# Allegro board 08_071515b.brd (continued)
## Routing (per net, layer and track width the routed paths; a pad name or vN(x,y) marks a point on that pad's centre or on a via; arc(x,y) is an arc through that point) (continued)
VDD_PLL: length 19.3
  TOP w0.203: U1.K6 v1(29.02,54.14) ; U1.L6 v1(29.02,52.54) ; U1.M7 v1(29.82,51.74)
  TOP w0.305: U1.K6 U1.L6 ; U1.L7 U1.M7
  BOTTOM w0.305: 29.73,53.23 C242.1 29.69,54.14 v1(29.02,54.14) ; 29.73,53.23 C244.1 ; 29.73,53.23 C46.1 25.74,53.23 25.53,53.44 C243.1 20.17,53.44 ; C244.1 29.82,52.48 v1(29.82,51.74) ; C244.1 29.69,52.54 v1(29.02,52.54)
  BOTTOM w0.508: 20.17,53.44 C47.1 18.39,53.44 L1.2
VDD_REF: length 163.5
  TOP w0.203: U1.P5 v1(28.22,50.14) U1.R5
  TOP w0.305: v1(33.82,55.74) U1.G11 U1.G10 ; U1.T9 v1(31.42,48.54) ; v1(46.22,48.54) C129.1 ; v1(46.22,50.14) C67.1 ; v1(33.82,43.34) C149.1 ; v1(46.22,46.94) C72.1 ; U1.T15 v1(37.02,48.54) ; U1.T10 v1(32.22,48.54) ; v1(43.02,50.14) C133.1 ; v1(43.02,46.94) C62.1 ; U1.M15 v1(37.02,51.74) ; C109.1 34.99,43.71 v1(35.42,44.14) ; U1.T6 v1(29.82,48.54) U1.T7 ; C82.1 v1(43.02,48.54) ; U1.T8 v1(30.62,48.54) ; v1(6.98,8.26) R43.1 ; U1.T13 v1(35.42,48.54) ; v1(3.17,8.38) R42.1 ; U1.N15 v1(37.02,50.94) ; U1.T12 v1(34.62,48.54) ; U1.P15 v1(37.02,50.14) ; U1.R15 v1(37.02,49.34) ; v1(46.22,51.74) C77.1 ; C87.1 v1(46.22,45.34) ; U1.T11 v1(33.82,48.54) ; U1.T14 v1(36.22,48.54)
  TOP w0.508: v2(13.59,47.75) C201.1 14.36,46.77 Y2.4 12.71,46.48 R113.1 ; v2(59.69,51.43) R16.1 ; FL3.1 v2(57.58,49.78)
  TOP w0.635: v2(59.69,54.48) 59.25,54.93 FL2.1
  L5_SIG w0.508: v2(28.19,44.2) 24.38,44.2 22.86,45.72 15.62,45.72 v2(13.59,47.75)
  L6_PWR w0.508: 62.15,57.99 TP4.1 60.02,57.99
  BOTTOM w0.305: v1(43.02,46.94) C121.1 ; v1(50.55,49.4) 50.55,48.62 C57.1 51.31,48.62 v1(51.31,49.4) ; C105.1 v1(46.22,50.14) ; C145.1 v1(43.02,48.54) ; C101.1 v1(46.22,46.94) ; v1(46.22,45.34) C125.1 ; C113.1 v1(43.02,50.14) ; C137.1 34.53,55.74 v1(33.82,55.74) ; C92.1 v1(46.22,51.74) ; C149.1 v1(33.82,43.34) ; C141.1 v1(46.22,48.54) ; v1(43.02,45.34) C97.1
  BOTTOM w0.381: v1(3.17,8.38) 3.73,7.82 6.55,7.82 v1(6.98,8.26) 8.13,8.26 10.35,10.48 19.75,10.48 20.45,11.18 22.86,11.18 24.13,9.91 35.11,9.91 35.62,10.41 37.47,10.41 38.1,9.78 48.39,9.78 49.02,10.41 49.02,16.38 47.85,17.56 47.85,20.29 46.67,21.46 46.67,25.15 47.5,25.97 47.5,27.81 48.01,28.32 51.44,28.32 51.82,28.7 51.82,43.56 53.09,44.83 53.09,50.67 53.85,51.43 v2(59.69,51.43) ; v1(35.42,44.14) 35.42,43.44 C52.1 36.22,43.44 v1(36.22,44.14)
  vias: v2(60.45,57.53) v2(60.45,56.77) v2(60.45,56.01) v2(61.47,57.53) v2(61.47,56.77) v2(61.47,56.01)
AUDIO_CLK: length 8.1
  BOTTOM w0.14: J3.40 8.25,31.88 8.26,31.88 9.65,31.88 10.16,31.37 11.05,31.37 12.19,32.51 R141.2
CLK1: length 6.5
  BOTTOM w0.14: R142.2 10.69,29.18 10.22,29.65 10.22,30.54 9.52,31.24 J3.42
CLK2: length 7.5
  BOTTOM w0.14: R144.2 11.87,27.81 11.3,28.38 10.48,28.38 9.53,29.34 9.53,30.35 9.27,30.61 J3.44
CON_RESET_IN*: length 85.9
  TOP w0.14: U11.2 56.26,38.73 55.82,38.29 v1(54.61,38.29)
  L5_SIG w0.127: v1(54.23,12.45) 53.59,13.08 53.59,20.07 53.98,20.45 54.85,20.45 55.37,20.97 55.37,21.84 55.12,22.1 54.23,22.1 53.7,22.63 53.7,37.38 v1(54.61,38.29)
  L8_SIG w0.127: v1(54.23,12.45) 51.82,12.45 48.77,9.4 39.5,9.4 38.67,8.57 11.75,8.57 8,12.32 8,13.72 v1(8.51,14.22)
  BOTTOM w0.14: J3.96 6.91,14.22 v1(8.51,14.22) ; R62.2 v1(54.61,38.29)
DAI0_PIN01: length 60.8
  TOP w0.203: U1.Y8 v1(30.62,45.34)
  L8_SIG w0.127: v1(59.14,13.46) 58.65,13.46 57.79,13.46 55.93,15.32 55.93,27.13 55.25,27.81 55.25,29.59 54.61,30.23 54.61,31.24 55.12,31.75 55.12,35.69 54.74,36.07 54.1,36.07 50.55,39.62 48.9,39.62 47.4,38.13 42.55,38.13 41.13,39.54 40.36,39.54 40.09,39.54 40.09,39.54 40.05,39.54 38.84,40.74 34.86,40.74 34.17,40.06 33.22,40.06 32.89,40.39 30.35,40.39 29.86,40.88 29.86,44.58 v1(30.62,45.34)
  BOTTOM w0.14: J1.3 v1(59.14,13.46)
DAI0_PIN02: length 60.9
  TOP w0.203: U1.V9 v1(31.42,46.94)
  L8_SIG w0.127: v1(31.42,46.94) 31.42,46.91 31.03,46.53 31.03,44.88 30.19,44.03 30.19,42.33 30.86,41.66 32.26,41.66 33.53,40.39 34.04,40.39 34.72,41.07 39.02,41.07 40.22,39.87 41.27,39.87 42.68,38.46 47.22,38.46 48.77,40.01 50.8,40.01 54.36,36.45 55.18,36.45 55.58,36.05 55.58,28.12 56.26,27.43 56.26,15.62 57.78,14.1 v1(58.42,14.1)
  BOTTOM w0.14: J1.5 v1(58.42,14.1)
DAI0_PIN03: length 56.5
  TOP w0.203: U1.W9 v1(31.42,46.14)
  L8_SIG w0.127: v1(59.14,14.73) 59.14,15.26 58.4,16 58.17,16 56.92,17.25 56.92,27.79 56.39,28.32 56.39,37.47 56.01,37.85 53.98,37.85 50.89,40.93 40.1,40.93 39.24,41.78 33.15,41.78 32.51,42.42 31.88,42.42 31.46,42.84 31.46,44.28 31.83,44.66 31.83,45.73 v1(31.42,46.14)
  BOTTOM w0.14: J1.7 v1(59.14,14.73)
DAI0_PIN04: length 56.5
  TOP w0.203: U1.Y9 v1(31.42,45.34)
  L8_SIG w0.127: v1(58.42,15.37) 57.78,15.37 56.59,16.56 56.59,27.61 56.01,28.19 56.01,36.45 55.63,36.83 54.48,36.83 50.93,40.39 48.64,40.39 47.04,38.79 42.82,38.79 41.41,40.2 40.36,40.2 39.16,41.4 33.02,41.4 32.38,42.04 31.75,42.04 31.05,42.74 31.05,44.39 31.42,44.76 v1(31.42,45.34)
  BOTTOM w0.14: J1.9 v1(58.42,15.37)
DAI0_PIN05: length 56.2
  TOP w0.203: U1.W10 v1(32.22,46.14)
  L8_SIG w0.127: v1(61.5,16) 57.58,19.92 57.58,28.06 57.15,28.49 57.15,39.5 56.82,39.83 53.75,39.83 51.87,41.71 40.63,41.71 39.79,42.55 33.4,42.55 32.65,43.29 32.65,45.71 v1(32.22,46.14)
  BOTTOM w0.14: v1(61.5,16) 61.5,16 J1.11
DAI0_PIN06: length 56.3
  TOP w0.203: U1.V10 v1(32.22,46.94)
  L8_SIG w0.127: v1(32.22,46.94) 33.02,46.14 33.02,43.43 33.55,42.91 39.9,42.91 40.77,42.04 52.07,42.04 53.34,40.77 56.39,40.77 57.53,39.62 57.53,28.58 57.91,28.2 57.91,20.22 v1(61.5,16.64)
  BOTTOM w0.14: J1.13 v1(61.5,16.64)
DAI0_PIN07: length 53.4
  TOP w0.203: U1.Y10 v1(32.22,45.34)
  L8_SIG w0.127: v1(32.22,45.34) 32.22,44.54 31.79,44.11 31.79,42.97 31.96,42.8 32.64,42.8 33.27,42.16 39.5,42.16 40.39,41.28 51.05,41.28 53.47,38.86 56.52,38.86 56.77,38.61 56.77,28.41 57.25,27.92 57.25,19.16 v1(59.14,17.27)
  BOTTOM w0.14: J1.15 v1(59.14,17.27)
DAI0_PIN08: length 56.7
  TOP w0.203: U1.W11 v1(33.82,46.14)
  L8_SIG w0.127: v1(61.5,17.91) 61.98,17.91 61.98,17.91 62.23,17.91 62.53,18.21 62.53,18.75 61.6,19.68 60.83,19.68 60.2,20.32 60.2,30.73 59.56,31.37 59.56,42.42 59.05,42.93 57.4,42.93 57.02,43.31 48.26,43.31 46.99,44.58 34.42,44.58 34.23,44.76 34.23,45.73 v1(33.82,46.14)
  BOTTOM w0.14: J1.17 v1(61.5,17.91)
DAI0_PIN09: length 55.6
  TOP w0.203: U1.V11 v1(33.82,46.94)
  L8_SIG w0.127: v1(33.82,46.94) 33.4,46.52 33.4,44.45 34.44,43.41 40.03,43.41 41.02,42.42 52.58,42.42 53.21,41.78 56.01,41.78 58.67,39.12 58.67,32.38 58.37,32.08 58.37,30.53 59.31,29.59 59.31,19.94 60.71,18.54 61.62,18.54 v1(62.1,18.54)
  BOTTOM w0.14: J1.19 v1(62.1,18.54)
DAI0_PIN10: length 53.3
  TOP w0.203: U1.Y11 v1(33.82,45.34)
  L8_SIG w0.127: v1(61.5,19.18) 60.71,19.18 59.82,20.07 59.82,30.48 59.23,31.06 59.23,42.11 58.8,42.55 57.15,42.55 56.72,42.98 48.34,42.98 48.34,42.98 48.12,42.98 47.67,43.43 40.64,43.43 40.39,43.69 34.8,43.69 33.82,44.67 v1(33.82,45.34)
  BOTTOM w0.14: J1.21 v1(61.5,19.18)
DAI0_PIN11: length 56.6
  TOP w0.203: U1.Y12 v1(34.62,45.34)
  L8_SIG w0.127: v1(62.1,19.81) 61.9,20.02 61.01,20.02 60.58,20.45 60.58,30.99 59.94,31.62 59.94,45.34 59.44,45.85 56.86,45.85 55.46,44.45 47.92,44.45 46.52,45.85 45.21,45.85 44.32,44.95 43.18,44.95 35.01,44.95 v1(34.62,45.34)
  BOTTOM w0.14: J1.23 v1(62.1,19.81)
DAI0_PIN12: length 57.8
  TOP w0.203: U1.W12 v1(34.62,46.14)
  L8_SIG w0.127: v1(34.62,46.14) 34.62,46.15 34.23,46.54 34.23,47.13 34.46,47.35 41.89,47.35 42.04,47.5 46.61,47.5 47.88,46.23 48.9,46.23 49.45,45.67 53.92,45.67 55.25,46.99 59.78,46.99 61.04,45.73 61.04,32.31 62.23,31.11 62.23,21.18 v1(61.5,20.45)
  BOTTOM w0.14: J1.25 v1(61.5,20.45)
DAI0_PIN19: length 49.6
  TOP w0.203: U1.W13 v1(35.42,46.14)
  L8_SIG w0.127: v1(35.42,46.14) 35.83,45.73 42.55,45.73 43.05,46.23 46.61,46.23 48.01,44.83 55.37,44.83 56.77,46.23 59.56,46.23 60.33,45.47 60.33,31.88 60.96,31.24 60.96,25.43 v1(61.5,24.89)
  BOTTOM w0.14: J1.39 v1(61.5,24.89)
DAI0_PIN20: length 50
  TOP w0.203: U1.V12 v1(34.62,46.94)
  L8_SIG w0.127: v1(61.5,25.53) 61.29,25.74 61.29,31.55 60.71,32.13 60.71,45.59 59.69,46.61 56.64,46.61 55.25,45.21 49.4,45.21 48.83,45.78 47.61,45.78 46.86,46.53 35.03,46.53 v1(34.62,46.94)
  BOTTOM w0.14: J1.41 v1(61.5,25.53)
DAI1_PIN01: length 56.3
  TOP w0.203: U1.R20 v1(41.02,49.34)
  L4_SIG w0.127: v1(54.27,13.46) 54.65,13.84 54.65,14.32 54.94,14.61 58.29,14.61 58.85,15.16 59.49,15.16 60.15,15.82 60.15,27.33 58.85,28.63 58.85,29.9 57.94,30.81 57.94,33.05 53.64,37.34 53.64,38.59 52.05,40.18 52.05,44.85 51.31,45.59 51.31,47.12 49.09,49.34 v1(41.02,49.34)
  BOTTOM w0.14: J1.4 v1(54.27,13.46)
DAI1_PIN02: length 57.6
  TOP w0.203: U1.P18 v1(39.42,50.14)
  L4_SIG w0.127: v1(55.16,14.1) 55.66,13.59 58.65,13.59 60.48,15.41 60.48,27.58 59.18,28.88 59.18,30.16 58.29,31.05 58.29,33.16 53.98,37.47 53.98,39.88 52.38,41.47 52.38,47.06 51.82,47.62 51.44,47.62 49.35,49.71 42.08,49.71 42.04,49.75 39.81,49.75 v1(39.42,50.14)
  BOTTOM w0.14: J1.6 v1(55.16,14.1)
DAI1_PIN03: length 55.7
  TOP w0.203: U1.R18 v1(39.42,49.34)
  L4_SIG w0.127: v1(39.42,49.34) 39.81,48.95 42.1,48.95 42.16,49.02 46.74,49.02 47.88,47.88 50.04,47.88 50.9,47.02 50.9,45.53 51.69,44.75 51.69,40.08 53.31,38.45 53.31,37.2 57.39,33.13 57.39,33.12 57.58,32.93 57.58,28.53 59.82,26.29 59.82,16.97 59.36,16.51 58.93,16.51 58.29,15.87 57.66,15.87 56.72,14.94 54.47,14.94 v1(54.27,14.73)
  BOTTOM w0.14: J1.8 v1(54.27,14.73)
DAI1_PIN04: length 47.8
  TOP w0.203: U1.T20 v1(41.02,48.54)
  L4_SIG w0.127: v1(55.16,15.37) 57.15,17.36 57.15,19.94 57.81,20.6 57.81,27.69 57.25,28.25 57.25,32.79 57.06,32.98 57.06,32.99 52.98,37.06 52.98,38.32 51.36,39.94 51.36,44.61 50.57,45.4 50.57,46.71 49.78,47.5 47.37,47.5 46.91,47.96 42.09,47.96 41.5,48.54 v1(41.02,48.54)
  BOTTOM w0.14: J1.10 v1(55.16,15.37)
DAI1_PIN05: length 46.7
  TOP w0.203: U1.U20 v1(41.02,47.74)
  L4_SIG w0.127: v1(41.02,47.74) 41.29,47.74 41.66,47.37 46.48,47.37 48.01,45.85 49.19,45.85 50.7,44.34 50.7,43.62 50.7,39.67 52.32,38.04 52.32,36.79 56.4,32.72 56.4,32.71 56.59,32.52 56.59,27.98 57.15,27.41 57.15,20.87 56.46,20.19 56.46,17.97 55.64,17.15 55.63,17.15 54.86,17.14 54.27,16.55 v1(54.27,16)
  BOTTOM w0.14: J1.12 v1(54.27,16)
DAI1_PIN06: length 46.3
  TOP w0.203: U1.T19 v1(40.22,48.54)
  L4_SIG w0.127: v1(40.22,48.54) 40.63,48.13 41.41,48.13 41.88,47.65 46.71,47.65 48.13,46.23 49.27,46.23 51.03,44.47 51.03,43.93 51.03,39.81 52.65,38.18 52.65,36.93 56.73,32.85 56.73,32.84 56.92,32.66 56.92,28.11 57.48,27.55 57.48,20.74 56.79,20.05 56.79,17.81 55.63,16.64 v1(55.16,16.64)
  BOTTOM w0.14: J1.14 v1(55.16,16.64)
DAI1_PIN07: length 46.4
  TOP w0.203: U1.U19 v1(40.22,47.74)
  L4_SIG w0.127: v1(54.27,17.27) 54.47,17.48 55.5,17.48 56.13,18.11 56.13,20.32 56.77,20.96 56.77,27.33 56.26,27.84 56.26,32.38 56.07,32.57 56.07,32.58 51.94,36.7 51.94,37.47 51.56,37.85 50.55,37.85 50.37,38.03 50.37,44.2 49.86,44.71 48.58,44.71 46.74,46.55 41.97,46.55 41.17,47.35 40.61,47.35 v1(40.22,47.74)
  BOTTOM w0.14: J1.16 v1(54.27,17.27)
DAI1_PIN08: length 57
  TOP w0.203: U1.R19 v1(40.22,49.34)
  L5_SIG w0.127: v1(55.16,17.91) 57.62,17.91 60.68,20.97 60.68,45.88 59.31,47.24 54.1,47.24 52.53,45.67 49.58,45.67 49.02,46.23 44.45,46.23 41.75,48.93 40.63,48.93 v1(40.22,49.34)
  BOTTOM w0.14: J1.18 v1(55.16,17.91)
DAI1_PIN09: length 58.2
  TOP w0.203: U1.T18 v1(39.42,48.54)
  L5_SIG w0.127: v1(54.27,18.54) 57.79,18.54 60.35,21.11 60.35,45.74 59.18,46.91 54.24,46.91 52.66,45.34 49.44,45.34 48.94,45.85 43.55,45.85 41.28,48.13 39.83,48.13 v1(39.42,48.54)
  BOTTOM w0.14: J1.20 v1(54.27,18.54)
DAI1_PIN10: length 55.6
  TOP w0.203: U1.U18 v1(39.42,47.74)
  L5_SIG w0.127: v1(39.42,47.74) 39.81,47.35 41.42,47.35 42.23,46.55 42.23,45.53 42.93,44.83 52.62,44.83 54.38,46.58 59.04,46.58 60.02,45.6 60.02,21.35 57.85,19.18 v1(55.16,19.18)
  BOTTOM w0.14: J1.22 v1(55.16,19.18)
DAI1_PIN11: length 41.2
  TOP w0.203: U1.V19 v1(40.22,46.94)
  L4_SIG w0.127: v1(54.27,19.81) 54.27,20.3 54.42,20.45 54.74,20.45 56.01,21.72 56.01,27.05 55.56,27.5 55.56,31.05 53.21,33.4 53.21,34.16 51.82,35.56 50.67,35.56 49.53,36.7 49.53,42.1 46.86,44.77 46.86,45.45 46.47,45.85 41.31,45.85 v1(40.22,46.94)
  BOTTOM w0.14: J1.24 v1(54.27,19.81)
DAI1_PIN12: length 39.1
  TOP w0.203: U1.V20 v1(41.02,46.94)
  L4_SIG w0.127: v1(55.46,20.45) 56.39,21.37 56.39,27.24 55.92,27.7 55.92,31.16 53.59,33.49 53.59,34.54 51.56,36.58 50.8,36.58 50.04,37.34 50.04,44.06 49.72,44.38 48.33,44.38 46.58,46.13 41.83,46.13 v1(41.02,46.94)
  BOTTOM w0.14: J1.26 v1(55.46,20.45)
DAI1_PIN19: length 49.3
  TOP w0.203: U1.V17 v1(38.62,46.94)
  L5_SIG w0.127: v1(55.46,24.89) 58.87,24.89 59.69,25.72 59.69,45.47 58.9,46.25 54.51,46.25 52.71,44.45 42.67,44.45 40.6,46.53 39.03,46.53 v1(38.62,46.94)
  BOTTOM w0.14: J1.40 v1(55.46,24.89)
DAI1_PIN20: length 33.2
  TOP w0.203: U1.W18 v1(39.42,46.14)
  L4_SIG w0.127: v1(55.46,25.53) 54.99,26 54.99,29.97 52.71,32.26 52.71,33.91 52.32,34.29 50.8,34.29 49.15,35.94 49.15,42.01 46.33,44.83 41.66,44.83 40.76,45.73 39.83,45.73 39.42,46.13 v1(39.42,46.14)
  BOTTOM w0.14: v1(55.46,25.53) J1.42
DMC0_A00: length 41.1
  TOP w0.14: U8.N3 v1(36.22,74.34)
  TOP w0.203: U1.D19 v1(40.22,58.94)
  L4_SIG w0.127: v1(42.62,59.74) 43.19,60.31 44.22,61.34 44.22,64.61 44.07,64.76 44.07,70.14 44.27,70.34 45.14,70.34 45.34,70.54 45.34,75.74 44.94,76.14 36.82,76.14 36.62,75.94 U8.N3 v1(36.22,74.34)
  BOTTOM w0.14: v1(42.62,59.74) 42.22,59.34 40.62,59.34 v1(40.22,58.94) ; v1(36.22,74.34) 36.22,74.74 37.22,75.74 37.42,75.74 37.62,75.54 37.62,75.34 37.82,75.14 38.02,75.14 38.22,75.34 38.22,75.47 38.42,75.67 38.62,75.67 38.82,75.47 38.82,75.34 39.02,75.14 39.22,75.14 39.42,75.34 39.42,75.54 39.22,75.74 39.22,75.94 39.42,76.14 41.37,76.14 41.42,76.19 41.93,76.19 RN1.1
DMC0_A01: length 41.3
  TOP w0.14: U8.P7 v1(37.02,78.34)
  TOP w0.203: U1.D20 v1(41.02,58.94)
  L8_SIG w0.127: v1(41.02,58.94) 40.62,59.34 39.22,59.34 39.02,59.14 39.02,58.74 38.82,58.54 38.42,58.54 38.22,58.74 38.22,59.94 38.42,60.14 38.82,60.14 39.02,60.34 39.02,63.34 38.82,63.54 37.62,63.54 37.42,63.74 37.42,63.94 37.62,64.14 37.82,64.14 38.02,63.94 38.82,63.94 39.02,64.14 39.02,64.34 38.82,64.54 38.02,64.54 37.82,64.74 37.82,68.81 38.22,69.21 38.22,69.74 37.82,70.14 37.82,70.34 38.02,70.54 38.02,71.34 37.82,71.54 37.82,71.74 38.02,71.94 38.22,71.94 38.42,72.14 38.42,72.34 38.22,72.54 38.22,74.94 37.82,75.34 37.82,75.54 38.02,75.74 38.22,75.74 38.42,75.54 38.62,75.54 38.82,75.74 38.82,75.94 38.62,76.14 37.22,76.14 37.02,76.34 v1(37.02,78.34)
  BOTTOM w0.14: RN3.2 42.01,79.89 41.42,79.89 41.17,80.14 41.02,80.14 40.82,80.34 40.82,80.54 41.02,80.74 41.02,80.94 40.82,81.14 40.42,81.14 40.22,80.94 40.22,80.74 40.42,80.54 40.42,80.34 40.22,80.14 39.62,80.14 39.42,79.94 39.42,79.42 39.5,79.34 39.5,78.94 39.3,78.74 37.42,78.74 37.42,78.74 v1(37.02,78.34)
DMC0_A02: length 41.4
  TOP w0.127: U1.C20 41.42,59.34 v1(41.82,59.74)
  TOP w0.14: U8.P3 v1(37.02,74.34)
  L4_SIG w0.127: v1(37.02,74.34) 37.02,75.54 37.22,75.74 44.43,75.74 44.83,75.34 44.83,71.14 44.63,70.94 43.42,70.94 43.22,70.74 43.22,66.34 43.02,66.14 42.55,66.14 42.42,66.01 42.42,65.66 42.55,65.53 43.56,65.53 43.69,65.4 43.69,64.39 43.82,64.26 43.82,61.94 43.62,61.74 43.42,61.74 43.22,61.94 43.02,61.94 42.82,61.74 42.42,61.74 42.06,62.1 41.75,62.1 41.62,61.98 41.62,60.34 41.82,60.14 v1(41.82,59.74)
  BOTTOM w0.14: v1(37.02,74.34) 37.42,73.94 39.14,73.94 39.42,73.66 39.42,71.94 39.62,71.74 41.22,71.74 41.42,71.94 41.42,73.35 41.56,73.49 42.01,73.49 RN2.2
DMC0_A03: length 41.3
  TOP w0.14: U8.N2 v1(36.22,73.54)
  TOP w0.203: U1.C19 v1(40.22,59.74)
  L4_SIG w0.127: v1(36.22,61.34) 36.22,61.94 35.62,62.54 35.22,62.54 35.02,62.74 35.02,64.94 35.22,65.14 36.42,65.14 36.62,65.34 36.62,65.73 37.02,66.13 37.02,66.41 37.22,66.61 37.42,66.61 37.62,66.41 37.82,66.41 38.02,66.61 38.02,66.81 37.82,67.01 37.22,67.01 37.02,67.21 37.02,67.41 37.22,67.61 37.42,67.61 37.62,67.41 37.82,67.41 38.02,67.61 38.02,67.81 37.82,68.01 37.22,68.01 37.02,68.21 37.02,68.41 37.22,68.61 37.42,68.61 37.62,68.41 37.82,68.41 38.02,68.61 38.02,68.81 37.82,69.01 37.22,69.01 37.02,69.21 37.02,70.34 37.22,70.54 37.42,70.54 37.62,70.34 37.82,70.34 38.02,70.54 38.02,70.74 37.82,70.94 37.22,70.94 37.02,71.14 37.02,71.34 37.22,71.54 37.42,71.54 37.62,71.34 37.82,71.34 38.02,71.54 38.02,71.74 37.82,71.94 36.02,71.94 35.82,72.14 35.82,73.14 v1(36.22,73.54)
  BOTTOM w0.14: RN5.2 36.9,70.2 37.04,70.34 37.82,70.34 38.02,70.54 38.02,70.74 37.62,71.14 37.42,71.14 37.22,70.94 37.02,70.94 36.82,71.14 36.82,71.34 37.02,71.54 37.12,71.54 37.32,71.74 37.32,71.84 36.62,72.54 36.62,73.86 36.54,73.94 36.32,73.94 36.22,73.84 v1(36.22,73.54) ; v1(36.22,61.34) 35.82,60.94 35.82,59.57 36.05,59.34 U1.C19 v1(40.22,59.74)
DMC0_A04: length 41
  TOP w0.14: U8.P8 v1(37.02,79.14)
  TOP w0.203: U1.A19 v1(40.22,61.34)
  L8_SIG w0.127: v1(40.22,61.34) 40.22,62.34 39.82,62.74 39.82,63.74 39.42,64.14 39.42,64.74 39.22,64.94 38.42,64.94 38.22,65.14 38.22,66.54 38.36,66.67 38.68,66.67 38.82,66.54 38.82,65.94 39.02,65.74 39.22,65.74 39.42,65.94 39.42,66.81 39.22,67.01 38.42,67.01 38.22,67.21 38.22,67.41 38.42,67.61 38.82,67.61 39.02,67.41 39.22,67.41 39.42,67.61 39.42,67.81 39.22,68.01 38.42,68.01 38.22,68.21 38.22,68.41 38.42,68.61 38.82,68.61 39.02,68.41 39.22,68.41 39.42,68.61 39.42,68.81 39.22,69.01 38.82,69.01 38.62,69.21 38.62,69.74 38.82,69.94 39.22,69.94 39.42,70.14 39.42,70.34 39.22,70.54 39.02,70.54 38.82,70.34 38.62,70.34 38.42,70.54 38.42,70.74 38.62,70.94 39.22,70.94 39.42,71.14 39.42,71.34 39.22,71.54 39.02,71.54 38.82,71.74 38.82,72.34 39.02,72.54 39.02,74.94 39.22,75.14 39.22,76.34 39.02,76.54 37.62,76.54 37.42,76.74 U8.P8 v1(37.02,79.14)
  BOTTOM w0.14: v1(37.02,79.14) 37.3,79.42 37.42,79.54 37.42,80.34 37.82,80.74 37.82,82.14 38.02,82.34 39.17,82.34 39.37,82.54 39.37,84.34 39.17,84.54 38.12,84.54 RN4.1
DMC0_A05: length 41.3
  TOP w0.14: U8.P2 v1(37.02,73.54)
  TOP w0.203: U1.B20 v1(41.02,60.54)
  L4_SIG w0.127: v1(37.02,73.54) 37.42,73.14 39.22,73.14 39.62,73.54 39.82,73.54 40.02,73.34 40.02,73.14 39.82,72.94 39.82,72.74 40.02,72.54 40.02,67.79 39.79,67.56 38.99,67.56 38.79,67.36 38.79,67.16 38.99,66.96 39.19,66.96 39.39,67.16 39.79,67.16 39.99,66.96 39.99,66.76 39.79,66.56 38.99,66.56 38.79,66.36 38.79,66.16 38.99,65.96 39.19,65.96 39.39,66.16 39.79,66.16 39.99,65.96 39.99,65.76 39.79,65.56 39.19,65.56 38.99,65.36 38.99,65.11 38.82,64.94 38.82,64.74 39.02,64.54 39.22,64.54 39.42,64.34 39.42,64.14 39.22,63.94 38.42,63.94 38.22,64.14 38.22,64.74 38.42,64.94 38.42,65.14 38.22,65.34 38.02,65.34 37.82,65.14 37.82,64.14 37.62,63.94 37.42,63.94 37.02,64.34 36.82,64.34 36.62,64.14 36.62,63.94 36.82,63.74 36.82,63.54 36.62,63.34 36.62,62.74 37.02,62.34 37.02,61.94 37.22,61.74 38.84,61.74 39.03,61.56 39.03,61.13 39.22,60.94 40.62,60.94 40.75,60.81 v1(41.02,60.54)
  BOTTOM w0.14: RN5.3 37.39,68.63 37.39,69.8 37.53,69.94 38.22,69.94 38.42,69.74 38.82,69.74 39.02,69.94 39.45,69.94 39.65,70.14 39.65,70.34 39.45,70.54 38.82,70.54 37.82,71.54 37.82,71.94 37.42,72.34 37.42,73.14 v1(37.02,73.54)
DMC0_A06: length 41
  TOP w0.14: U8.R8 v1(37.82,79.14)
  TOP w0.203: U1.B18 v1(39.42,60.54)
  L8_SIG w0.127: v1(37.82,79.14) U8.R8 38.22,77.54 38.42,77.34 41.42,77.34 41.62,77.14 41.62,74.14 41.42,73.94 40.22,73.94 40.02,73.74 40.02,73.54 40.22,73.34 40.42,73.34 40.62,73.54 41.42,73.54 41.62,73.34 41.62,73.14 41.42,72.94 40.22,72.94 40.02,72.74 40.02,72.54 40.22,72.34 40.42,72.34 40.62,72.54 41.22,72.54 41.42,72.34 41.42,72.14 41.22,71.94 40.42,71.94 40.22,71.74 40.22,71.54 40.42,71.34 40.62,71.34 40.82,71.54 41.02,71.54 41.22,71.34 41.22,71.14 41.02,70.94 40.42,70.94 40.22,70.74 40.22,62.94 40.62,62.54 40.62,61.14 40.42,60.94 39.82,60.94 39.77,60.89 v1(39.42,60.54)
  BOTTOM w0.14: v1(37.82,79.14) 38.12,79.43 38.12,79.44 38.22,79.54 38.22,81.74 38.42,81.94 42.22,81.94 42.42,81.74 42.42,81.54 42.22,81.34 42.02,81.34 41.82,81.14 41.93,81.03 RN3.4
DMC0_A07: length 40.7
  TOP w0.14: U8.R2 v1(37.82,73.54)
  TOP w0.203: U1.A18 v1(39.42,61.34)
  L4_SIG w0.127: v1(39.42,61.34) 39.42,61.94 39.22,62.14 37.62,62.14 37.42,62.34 37.42,63.34 37.62,63.54 39.82,63.54 40.02,63.74 40.02,64.34 40.22,64.54 40.22,65.54 40.42,65.74 40.42,67.34 40.62,67.54 41.42,67.54 41.62,67.34 41.82,67.34 42.02,67.54 42.02,67.74 41.82,67.94 40.62,67.94 40.42,68.14 40.42,68.34 40.62,68.54 41.42,68.54 41.62,68.34 41.82,68.34 42.02,68.54 42.02,68.74 41.82,68.94 40.62,68.94 40.42,69.14 40.42,69.34 40.62,69.54 41.42,69.54 41.62,69.34 41.82,69.34 42.02,69.54 42.02,69.74 41.82,69.94 40.62,69.94 40.42,70.14 40.42,70.34 40.62,70.54 41.42,70.54 41.62,70.34 41.82,70.34 42.02,70.54 42.02,70.74 41.82,70.94 40.62,70.94 40.42,71.14 40.42,73.65 40.13,73.94 U8.R2 v1(37.82,73.54)
  BOTTOM w0.14: RN5.4 38.04,68.77 38.23,68.96 39.82,68.96 40.02,69.16 40.02,70.74 39.82,70.94 39.02,70.94 38.22,71.74 38.22,73.14 v1(37.82,73.54)
DMC0_A08: length 41.2
  TOP w0.14: U8.T8 v1(38.62,79.14)
  TOP w0.203: U1.A16 v1(37.82,61.34)
  L8_SIG w0.127: v1(38.62,79.14) U8.T8 39.02,78.34 39.22,78.14 42.62,78.14 42.77,77.99 42.77,69.29 42.62,69.14 41.22,69.14 41.02,68.94 41.02,68.74 41.22,68.54 41.62,68.54 41.82,68.74 42.02,68.74 42.22,68.54 42.22,68.34 42.02,68.14 41.22,68.14 41.02,67.94 41.02,62.37 41.42,61.97 41.42,60.14 v1(41.02,59.74)
  BOTTOM w0.14: RN3.3 41.62,80.39 41.42,80.59 41.42,81.34 41.22,81.54 38.82,81.54 38.62,81.34 38.62,81.04 38.76,80.9 38.98,80.9 39.22,81.14 39.62,81.14 39.82,80.94 39.82,80.74 39.62,80.54 39.22,80.54 39.02,80.34 39.02,79.54 38.86,79.38 v1(38.62,79.14) ; v1(37.82,61.34) 38.22,60.94 38.22,60.37 38.45,60.14 40.62,60.14 v1(41.02,59.74)
DMC0_A09: length 41.3
  TOP w0.14: U8.R3 v1(37.82,74.34)
  TOP w0.203: U1.B16 v1(37.82,60.54)
  L4_SIG w0.127: v1(37.82,74.34) 37.82,75.06 37.95,75.18 38.23,75.18 38.35,75.06 38.35,74.99 38.61,74.74 44.13,74.74 44.32,74.55 44.32,74.27 44.2,74.14 43.22,74.14 43.02,74.34 42.62,74.34 42.42,74.14 42.42,73.94 42.62,73.74 44.08,73.74 44.21,73.61 44.21,73.28 44.07,73.14 43.42,73.14 43.22,73.34 43.02,73.34 42.79,73.11 42.79,66.71 42.62,66.54 41.42,66.54 41.22,66.34 41.22,66.14 41.42,65.94 41.42,64.54 40.82,63.94 40.82,62.34 40.62,62.14 40.26,62.14 v1(39.82,62.14)
  BOTTOM w0.14: RN2.4 41.87,74.49 41.62,74.49 41.42,74.69 41.42,75.14 41.62,75.34 41.62,75.54 41.42,75.74 41.19,75.74 41,75.54 41,74.71 40.82,74.54 40.62,74.54 40.42,74.74 40.42,75.14 40.62,75.34 40.62,75.54 40.42,75.74 40.22,75.74 40.02,75.54 40.02,74.94 39.82,74.74 U8.R3 v1(37.82,74.34) ; v1(39.82,62.14) 39.44,61.76 37.59,61.76 37.42,61.59 37.42,60.88 37.76,60.54 v1(37.82,60.54)
DMC0_A10: length 41.2
  TOP w0.14: U8.L7 v1(34.62,78.34)
  TOP w0.203: U1.A15 v1(37.02,61.34)
  L8_SIG w0.127: v1(34.62,78.34) 34.62,77.94 34.82,77.74 34.82,77.54 34.62,77.34 34.62,74.94 35.02,74.54 35.02,73.34 34.62,72.94 34.62,61.94 35.02,61.54 35.02,57.94 35.22,57.74 35.62,57.74 35.82,57.94 35.82,59.94 36.02,60.14 36.42,60.14 36.62,59.94 36.62,57.94 36.82,57.74 37.22,57.74 37.42,57.94 37.42,60.94 v1(37.02,61.34)
  BOTTOM w0.14: v1(34.62,78.34) 34.62,78.04 34.52,77.94 34.32,77.94 34.22,78.04 34.22,81.14 34.42,81.34 34.84,81.34 35.22,81.72 35.22,82.3 34.84,82.68 34.29,82.68 34.06,82.9 34.06,84.19 RN7.1
DMC0_A11: length 41.3
  TOP w0.14: U8.R7 v1(37.82,78.34)
  TOP w0.203: U1.B15 v1(37.02,60.54)
  L8_SIG w0.127: v1(37.82,78.34) 37.82,77.14 38.02,76.94 41.02,76.94 41.22,76.74 41.22,76.54 41.02,76.34 40.82,76.34 40.62,76.54 39.82,76.54 39.62,76.34 39.62,76.14 39.82,75.94 41.02,75.94 41.22,75.74 41.22,75.54 41.02,75.34 40.82,75.34 40.62,75.54 39.82,75.54 39.62,75.34 39.62,75.14 39.82,74.94 41.02,74.94 41.22,74.74 41.22,74.54 41.02,74.34 40.82,74.34 40.62,74.54 39.82,74.54 39.62,74.34 39.62,71.74 39.82,71.54 v1(39.82,64.74)
  BOTTOM w0.14: v1(39.82,64.74) 39.82,62.83 39.09,62.1 36.96,62.1 36.62,61.77 36.62,60.92 37,60.54 v1(37.02,60.54) ; v1(37.82,78.34) 37.59,78.11 37.42,77.94 36.17,77.94 35.97,77.74 35.97,77.54 36.17,77.34 36.82,77.34 37.05,77.57 41.41,77.57 41.53,77.69 41.93,77.69 RN1.4
DMC0_A12: length 41.3
  TOP w0.14: U8.N7 v1(36.22,78.34)
  TOP w0.203: U1.B14 v1(36.22,60.54)
  L8_SIG w0.127: v1(36.22,78.34) 35.84,77.96 35.62,77.74 35.62,77.14 35.42,76.94 35.42,75.54 35.62,75.34 36.42,75.34 36.62,75.14 36.62,72.14 36.42,71.94 35.62,71.94 35.42,71.74 35.42,71.54 35.62,71.34 35.82,71.34 36.02,71.54 36.82,71.54 37.02,71.34 37.02,71.14 36.82,70.94 35.62,70.94 35.42,70.74 35.42,70.54 35.62,70.34 35.82,70.34 36.02,70.54 36.82,70.54 37.02,70.34 37.02,70.14 36.82,69.94 35.62,69.94 35.42,69.74 35.42,69.54 35.62,69.34 35.82,69.34 36.02,69.54 36.82,69.54 37.02,69.34 37.02,69.14 36.82,68.94 35.62,68.94 35.42,68.74 35.42,68.54 35.62,68.34 35.82,68.34 36.02,68.54 36.22,68.54 36.42,68.34 36.42,68.14 36.22,67.94 35.62,67.94 35.42,67.74 35.42,66.14 35.82,65.74 35.82,62.34 36.62,61.54 36.62,60.94 v1(36.22,60.54)
  BOTTOM w0.14: v1(36.22,78.34) 36.53,78.65 36.62,78.74 36.62,80.34 37.27,80.99 37.27,82.59 37.42,82.74 38.33,82.74 38.53,82.94 38.53,83.54 38.33,83.74 37.42,83.74 37.27,83.89 RN4.2
DMC0_A13: length 41.2
  TOP w0.14: v1(37.82,63.14) 37.82,62.71 37.59,62.48 36.2,62.48 35.82,62.11 U1.A14 ; U8.T3 v1(38.62,74.34)
  L4_SIG w0.127: v1(37.82,63.14) 38.42,62.54 38.82,62.54 39.42,63.14 39.62,63.14 40.02,62.74 40.22,62.74 40.42,62.94 40.42,64.14 41.02,64.74 41.02,65.74 40.82,65.94 40.82,66.74 41.02,66.94 42.22,66.94 42.42,67.14 42.42,71.14 42.22,71.34 41.02,71.34 40.82,71.54 40.82,71.74 41.02,71.94 41.22,71.94 41.42,71.74 42.22,71.74 42.42,71.94 42.42,72.34 42.22,72.54 41.62,72.54 41.42,72.34 41.02,72.34 40.82,72.54 40.82,72.74 41.02,72.94 42.22,72.94 42.42,73.14 42.42,73.34 42.22,73.54 42.02,73.54 41.82,73.34 41.02,73.34 40.82,73.54 40.82,73.74 41.02,73.94 41.22,73.94 41.42,73.74 41.62,73.74 41.82,73.94 41.82,74.14 41.62,74.34 v1(38.62,74.34)
  BOTTOM w0.14: RN2.3 42.01,73.99 41.22,73.99 41.02,73.79 41.02,73.54 40.82,73.34 40.48,73.34 40.28,73.14 40.28,72.94 40.48,72.74 40.82,72.74 41.02,72.54 41.02,72.34 40.82,72.14 40.02,72.14 39.82,72.34 39.82,73.54 40.22,73.94 40.22,74.14 40.02,74.34 v1(38.62,74.34)
DMC0_A14: length 41.4
  TOP w0.14: U1.A13 35.42,61.34 35.42,62.48 36.07,63.13 36.07,65.39 36.72,66.04 39.92,66.04 v1(40.62,65.34) ; U8.T7 v1(38.62,78.34)
  L8_SIG w0.127: v1(38.62,78.34) 38.62,77.94 38.82,77.74 42.22,77.74 42.42,77.54 42.42,74.74 42.22,74.54 42.22,72.74 42.42,72.54 42.42,71.94 42.22,71.74 41.82,71.74 41.62,71.54 41.62,71.34 41.82,71.14 42.22,71.14 42.42,70.94 42.42,70.74 42.22,70.54 40.82,70.54 40.62,70.34 40.62,70.14 40.82,69.94 41.02,69.94 41.22,70.14 41.91,70.14 42.04,70.01 42.04,69.67 41.91,69.54 40.82,69.54 40.62,69.34 v1(40.62,65.34)
  BOTTOM w0.14: RN3.1 41.87,79.39 41.2,79.39 41,79.19 41,78.94 41.2,78.74 41.42,78.74 41.62,78.54 41.62,78.34 41.42,78.14 40.98,78.14 40.82,77.98 40.62,77.98 40.42,78.18 40.42,78.34 40.62,78.54 40.62,78.74 40.42,78.94 40.42,79.14 40.62,79.34 40.62,79.54 40.42,79.74 40.22,79.74 40.02,79.54 40.02,78.54 39.82,78.34 v1(38.62,78.34)
DMC0_A15: length 41.1
  TOP w0.14: U8.M7 v1(35.42,78.34)
  TOP w0.203: U1.B13 v1(35.42,60.54)
  L8_SIG w0.127: v1(35.42,60.54) 35.82,60.94 35.82,61.54 35.02,62.34 35.02,72.14 35.22,72.34 35.62,72.34 35.82,72.54 35.82,74.74 35.62,74.94 35.22,74.94 35.02,75.14 35.02,77.14 35.22,77.34 35.22,77.94 35.02,78.14 35.02,79.94 34.62,80.34 33.82,80.34 33.62,80.54 33.62,80.74 33.82,80.94 34.02,80.94 34.22,80.74 34.82,80.74 35.02,80.54 35.22,80.54 35.42,80.74 35.42,80.94 35.22,81.14 34.62,81.14 34.42,81.34 34.42,81.54 34.62,81.74 35.42,81.74 35.82,81.34 35.82,78.74 v1(35.42,78.34)
  BOTTOM w0.14: v1(35.42,78.34) 35.02,78.74 34.82,78.74 34.62,78.94 34.62,80.74 34.82,80.94 35.22,80.94 35.62,81.34 35.62,82.14 35.82,82.34 35.82,83.94 35.48,84.28 35.48,84.6 35.56,84.68 35.88,84.68 36.02,84.54 36.02,84.44 RN4.4
DMC0_BA0: length 41.3
  TOP w0.14: U8.M2 v1(35.42,73.54)
  TOP w0.203: U1.B17 v1(38.62,60.54)
  L4_SIG w0.127: v1(38.62,60.54) 38.34,60.82 38.22,60.94 36.82,60.94 36.62,61.14 36.62,62.14 36.22,62.54 36.22,63.94 36.02,64.14 35.62,64.14 35.42,64.34 35.42,64.54 35.62,64.74 37.22,64.74 37.42,64.94 37.42,65.84 37.59,66.01 38.09,66.01 38.39,66.31 38.39,67.96 38.59,68.16 38.99,68.16 39.19,67.96 39.39,67.96 39.59,68.16 39.59,68.36 39.39,68.56 38.59,68.56 38.39,68.76 38.39,68.96 38.59,69.16 38.79,69.16 38.99,68.96 39.39,68.96 39.62,69.19 39.62,70.14 39.42,70.34 39.22,70.34 39.02,70.14 39.02,69.94 38.82,69.74 38.62,69.74 38.42,69.94 38.42,70.74 38.62,70.94 39.02,70.94 39.22,70.74 39.42,70.74 39.62,70.94 39.62,71.14 39.42,71.34 38.62,71.34 38.42,71.54 38.42,71.74 38.62,71.94 39.02,71.94 39.22,71.74 39.42,71.74 39.62,71.94 39.62,72.34 39.42,72.54 39.22,72.54 39.02,72.34 36.82,72.34 36.62,72.54 36.62,73.74 36.42,73.94 U8.M2 v1(35.42,73.54)
  BOTTOM w0.14: RN5.1 36.13,68.75 36.13,69.28 36.37,69.52 36.37,69.74 36.22,69.89 36.22,70.14 36.62,70.54 36.62,70.74 36.52,70.84 36.32,70.84 36.22,70.94 36.22,71.54 36.32,71.64 36.52,71.64 36.62,71.74 36.62,71.94 36.22,72.34 36.02,72.34 35.82,72.54 35.82,73.74 35.62,73.94 35.22,73.94 35.02,73.74 35.02,73.24 35.12,73.14 35.32,73.14 35.42,73.24 v1(35.42,73.54)
DMC0_BA1: length 41.2
  TOP w0.14: U8.N8 v1(36.22,79.14)
  TOP w0.203: U1.A17 v1(38.62,61.34)
  L8_SIG w0.127: v1(38.62,61.34) 38.62,61.83 38.62,62.54 38.42,62.74 38.22,62.74 38.02,62.54 38.02,62.34 38.22,62.14 38.22,61.94 38.02,61.74 37.82,61.74 37.62,61.94 37.62,62.54 37.42,62.74 36.62,62.74 36.22,63.14 36.22,63.94 36.42,64.14 37.02,64.14 37.22,64.34 37.22,64.54 37.02,64.74 36.82,64.74 36.62,64.54 36.42,64.54 36.22,64.74 36.22,64.94 36.42,65.14 37.22,65.14 37.42,65.34 37.42,65.74 37.22,65.94 36.42,65.94 36.22,66.14 36.22,66.34 36.42,66.54 37.22,66.54 37.42,66.74 37.42,66.94 37.22,67.14 36.62,67.14 36.42,66.94 36.02,66.94 35.82,67.14 35.82,67.34 36.02,67.54 37.22,67.54 37.42,67.74 37.42,75.54 37.22,75.74 36.02,75.74 35.82,75.94 35.82,76.74 36.02,76.94 36.42,76.94 36.62,77.14 U8.N8 v1(36.22,79.14)
  BOTTOM w0.14: v1(36.22,79.14) 35.97,79.39 35.82,79.54 35.22,79.54 35.02,79.74 35.02,80.34 35.22,80.54 35.62,80.54 35.82,80.74 35.82,80.94 36.02,81.14 36.5,81.14 36.7,81.34 36.7,81.54 36.5,81.74 36.34,81.74 36.22,81.86 36.22,82.04 36.32,82.14 36.65,82.14 36.78,82.27 36.78,82.38 36.62,82.54 36.62,82.74 36.82,82.94 37.02,82.94 37.22,83.14 37.22,83.34 36.77,83.79 RN4.3
DMC0_BA2: length 41.3
  TOP w0.127: v1(41.82,58.94) 41.02,58.14 40.22,58.14 U1.E19
  TOP w0.14: U8.M3 v1(35.42,74.34)
  L4_SIG w0.127: v1(41.82,58.94) 41.55,59.21 41.42,59.34 41.42,59.94 41.22,60.14 36.02,60.14 35.82,60.34 35.82,61.74 35.42,62.14 34.82,62.14 34.62,62.34 34.62,65.14 35.02,65.54 35.02,65.74 34.62,66.14 34.62,66.34 34.82,66.54 35.02,66.54 35.22,66.34 35.62,66.34 35.82,66.54 36.02,66.54 36.22,66.34 36.42,66.34 36.62,66.54 36.62,66.74 36.42,66.94 34.82,66.94 34.62,67.14 34.62,67.34 34.82,67.54 35.22,67.54 35.42,67.34 36.33,67.34 36.62,67.63 36.62,71.34 36.42,71.54 35.22,71.54 35.02,71.74 35.02,73.94 v1(35.42,74.34)
  BOTTOM w0.14: v1(35.42,74.34) U8.M3 35.82,74.94 37.62,76.74 37.82,76.74 38.02,76.54 38.02,76.34 38.22,76.14 38.42,76.14 38.62,76.34 38.62,76.54 38.82,76.74 39.02,76.74 39.15,76.61 39.59,76.61 39.72,76.74 40.98,76.74 41.03,76.69 42.07,76.69 RN1.2
DMC0_CAS*: length 40.9
  TOP w0.14: U8.K3 v1(33.82,74.34)
  TOP w0.203: U1.E20 v1(40.22,57.34)
  L4_SIG w0.127: v1(33.82,74.34) 33.82,75.44 33.62,75.64 33.42,75.64 33.22,75.44 33.22,74.74 33.42,74.54 33.42,73.34 33.02,72.94 33.02,67.14 32.62,66.74 32.62,57.24 32.82,57.04 33.12,57.04 33.32,57.24 33.32,57.54 33.52,57.74 34.02,57.74 34.22,57.54 34.22,56.24 34.42,56.04 34.82,56.04 35.02,56.24 35.02,56.74 35.22,56.94 38.02,56.94 38.22,57.14 38.22,57.54 38.42,57.74 39.82,57.74 39.99,57.57 v1(40.22,57.34)
  BOTTOM w0.14: v1(33.82,74.34) 34.22,73.94 34.22,72.14 34.42,71.94 35.22,71.94 35.42,71.74 35.42,71.54 35.02,71.14 35.02,70.94 35.42,70.54 35.42,69.68 35.28,69.54 34.34,69.54 34.2,69.4 RN6.3
DMC0_CK: length 33.6
  TOP w0.14: U8.J7 v1(33.02,78.34)
  TOP w0.203: U1.J20 v1(41.02,54.94)
  L8_SIG w0.076: v1(33.02,78.34) 33.02,77.89 32.89,77.76 32.89,74.97 32.62,74.7 32.62,73.19 32.89,72.92 32.89,68.91 32.52,68.54 32.52,67.01 32.89,66.64 32.89,57.27 34.32,55.84 34.75,55.84 35.05,55.54 35.05,54.86 35.31,54.61 35.88,54.61 35.95,54.54 U1.J20 40.7,54.62 v1(41.02,54.94)
  BOTTOM w0.14: v1(33.02,78.34) 32.97,78.29 R3.1
DMC0_CK*: length 33.7
  TOP w0.14: U8.K7 v1(33.82,78.34)
  TOP w0.203: U1.J19 v1(40.22,54.94)
  L8_SIG w0.076: v1(33.82,78.34) 33.8,78.31 33.8,78.1 33.78,77.98 33.78,77.72 33.66,77.6 33.53,77.6 33.4,77.72 33.26,77.72 33.15,77.61 33.15,74.97 33.42,74.7 33.42,73.19 33.15,72.92 33.15,68.74 32.82,68.41 32.82,67.14 33.15,66.81 33.15,57.41 34.42,56.14 34.91,56.14 35.31,55.74 35.31,54.99 35.43,54.86 35.69,54.86 35.81,54.99 35.81,55.26 35.9,55.34 40.21,55.34 40.31,55.24 40.31,55.03 v1(40.22,54.94)
  BOTTOM w0.14: R3.2 33.82,77.49 v1(33.82,78.34)
DMC0_CKE: length 41.2
  TOP w0.203: U1.H20 v1(41.02,55.74) ; U8.K9 v1(33.82,79.94)
  L8_SIG w0.127: v1(33.82,79.94) 33.82,79.94 34.42,79.94 34.62,79.74 34.62,79.14 34.22,78.74 34.22,57.14 34.42,56.94 38.02,56.94 38.22,56.74 38.22,56.34 38.42,56.14 40.92,56.14 41.02,56.04 v1(41.02,55.74)
  BOTTOM w0.14: RN7.2 33.56,83.69 33.44,83.57 32.89,83.57 32.77,83.44 32.77,83.15 32.89,83.02 33.15,83.02 33.27,82.9 33.27,82.68 33.15,82.55 32.89,82.55 32.77,82.42 32.77,82.27 32.89,82.14 34.02,82.14 34.22,82.34 34.62,82.34 34.82,82.14 34.82,81.94 34.62,81.74 34.02,81.74 33.82,81.54 v1(33.82,79.94)
DMC0_CS0*: length 39.7
  TOP w0.14: U8.L2 v1(34.62,73.54)
  TOP w0.203: U1.F20 v1(41.02,57.34)
  L4_SIG w0.127: v1(34.62,73.54) 34.62,72.34 34.22,71.94 34.22,71.34 34.42,71.14 36.02,71.14 36.22,70.94 36.22,68.94 36.02,68.74 35.02,68.74 34.82,68.94 34.42,68.94 34.22,68.74 34.22,68.54 34.42,68.34 36.02,68.34 36.22,68.14 36.22,67.94 36.02,67.74 35.62,67.74 35.42,67.94 34.42,67.94 34.22,67.74 34.22,61.94 34.42,61.74 34.82,61.74 35.02,61.54 35.02,59.54 35.22,59.34 40.42,59.34 40.62,59.14 40.62,58.34 40.82,58.14 41.62,58.14 41.82,57.94 41.82,57.54 41.62,57.34 v1(41.02,57.34)
  BOTTOM w0.14: RN6.4 34.84,68.47 34.98,68.33 35.3,68.33 35.42,68.45 35.42,69.08 35.82,69.48 35.82,71.94 35.42,72.34 34.82,72.34 34.62,72.54 v1(34.62,73.54)
DMC0_DQ00: length 33.4
  TOP w0.14: U8.E3 v1(29.82,74.34)
  TOP w0.203: U1.J2 v1(25.82,54.94)
  L4_SIG w0.127: v1(25.82,54.94) 26.22,55.34 26.22,55.94 26.42,56.14 26.82,56.14 27.02,55.94 27.02,55.54 27.22,55.34 27.62,55.34 27.82,55.54 27.82,55.94 28.02,56.14 28.42,56.14 28.62,56.34 28.62,66.96 28.42,67.16 27.62,67.16 27.42,67.36 27.42,67.56 27.62,67.76 28.42,67.76 28.62,67.96 28.62,68.16 28.42,68.36 27.22,68.36 27.02,68.56 27.02,68.76 27.22,68.96 28.42,68.96 28.62,69.16 28.62,69.94 28.22,70.34 28.22,70.54 28.62,70.94 28.62,72.94 28.42,73.14 27.22,73.14 27.02,73.34 27.02,73.74 27.22,73.94 28.42,73.94 28.62,74.14 28.62,74.54 28.82,74.74 29.42,74.74 29.6,74.56 29.6,74.56 v1(29.82,74.34)
DMC0_DQ01: length 33.4
  TOP w0.14: U8.F7 v1(30.62,78.34)
  TOP w0.203: U1.E1 v1(25.02,58.14)
  L4_SIG w0.127: v1(30.62,78.34) U8.F7 33.62,77.94 33.82,77.74 33.82,76.74 33.62,76.54 25.02,76.54 24.82,76.34 24.82,66.74 25.42,66.14 25.42,58.54 v1(25.02,58.14)
DMC0_DQ02: length 33.4
  TOP w0.14: U8.F2 v1(30.62,73.54)
  TOP w0.203: U1.H1 v1(25.02,55.74)
  L4_SIG w0.127: v1(25.02,55.74) U1.H1 25.42,54.74 25.62,54.54 29.22,54.54 29.42,54.74 29.42,61.74 29.02,62.14 29.02,68.14 29.22,68.34 29.22,68.54 29.02,68.74 29.02,68.94 29.22,69.14 29.62,69.14 29.82,69.34 29.82,69.54 29.62,69.74 29.22,69.74 29.02,69.94 29.02,70.14 29.22,70.34 30.42,70.34 30.62,70.54 30.62,70.74 30.42,70.94 29.22,70.94 29.02,71.14 29.02,71.34 29.22,71.54 30.42,71.54 30.62,71.74 30.62,71.94 30.42,72.14 29.62,72.14 29.42,72.34 29.42,73.74 29.62,73.94 30.22,73.94 30.34,73.82 v1(30.62,73.54)
DMC0_DQ03: length 33.5
  TOP w0.14: U8.F8 v1(30.62,79.14)
  TOP w0.203: U1.D1 v1(25.02,58.94)
  L4_SIG w0.127: v1(30.62,79.14) 30.22,78.74 29.62,78.74 29.42,78.54 29.42,78.14 29.22,77.94 28.82,77.94 28.62,78.14 28.62,78.54 28.42,78.74 28.02,78.74 27.82,78.54 27.82,78.14 27.62,77.94 27.22,77.94 27.02,78.14 27.02,78.54 26.82,78.74 26.42,78.74 26.22,78.94 26.02,78.94 25.82,78.74 25.82,78.54 26.02,78.34 26.02,78.14 25.82,77.94 25.02,77.94 24.02,76.94 24.02,66.14 24.62,65.54 24.62,62.34 24.02,61.74 24.02,60.14 24.42,59.74 24.42,59.54 24.02,59.14 24.02,58.14 24.22,57.94 24.42,57.94 24.62,58.14 24.62,58.34 24.42,58.54 24.42,58.74 24.62,58.94 v1(25.02,58.94)
DMC0_DQ04: length 33.4
  TOP w0.14: U8.H3 v1(32.22,74.34)
  TOP w0.203: U1.G2 v1(25.82,56.54)
  L4_SIG w0.127: v1(32.22,74.34) 31.82,73.94 31.82,67.54 31.02,66.74 31.02,56.14 30.62,55.74 30.62,53.54 30.42,53.34 24.42,53.34 24.22,53.54 24.22,55.94 24.42,56.14 25.42,56.14 v1(25.82,56.54)
DMC0_DQ05: length 33.4
  TOP w0.14: U8.H8 v1(32.22,79.14)
  TOP w0.203: U1.E2 v1(25.82,58.14)
  L4_SIG w0.127: v1(32.22,79.14) U8.H8 34.02,78.74 34.22,78.54 34.22,77.54 34.42,77.34 34.42,76.34 34.22,76.14 25.42,76.14 25.22,75.94 25.22,67.14 26.22,66.14 26.22,58.54 v1(25.82,58.14)
DMC0_DQ06: length 33.4
  TOP w0.14: U8.G2 v1(31.42,73.54)
  TOP w0.203: U1.J1 v1(25.02,54.94)
  L4_SIG w0.127: v1(25.02,54.94) 24.62,54.54 24.62,53.94 24.82,53.74 30.02,53.74 30.22,53.94 30.22,62.14 30.02,62.34 29.62,62.34 29.42,62.54 29.42,65.94 29.82,66.34 30.22,66.34 30.42,66.54 30.42,66.74 30.22,66.94 29.62,66.94 29.42,67.14 29.42,67.34 29.62,67.54 30.82,67.54 31.02,67.74 31.02,67.94 30.82,68.14 29.82,68.14 29.62,68.34 29.62,68.54 29.82,68.74 30.62,68.74 31.02,69.14 31.02,73.14 v1(31.42,73.54)
DMC0_DQ07: length 33.4
  TOP w0.14: U8.H7 v1(32.22,78.34)
  TOP w0.203: U1.G1 v1(25.02,56.54)
  L4_SIG w0.127: v1(32.22,78.34) 31.99,78.57 31.82,78.74 31.82,79.34 31.62,79.54 25.82,79.54 23.62,77.34 23.62,65.94 24.22,65.34 24.22,62.54 23.62,61.94 23.62,57.94 24.67,56.89 v1(25.02,56.54)
DMC0_DQ08: length 33.5
  TOP w0.14: U8.D7 v1(29.02,78.34)
  TOP w0.203: U1.C2 v1(25.82,59.74)
  BOTTOM w0.14: v1(29.02,78.34) 28.62,78.74 27.22,78.74 27.02,78.54 27.02,78.14 26.82,77.94 21.82,77.94 21.62,77.74 21.62,69.94 21.82,69.74 22.62,69.74 22.82,69.54 22.82,69.34 22.62,69.14 21.82,69.14 21.62,68.94 21.62,68.74 21.82,68.54 23.02,68.54 23.22,68.34 23.22,67.54 23.42,67.34 25.82,67.34 26.22,66.94 26.22,60.14 v1(25.82,59.74)
DMC0_DQ09: length 33.4
  TOP w0.14: U8.C3 v1(28.22,74.34)
  TOP w0.203: U1.B6 v1(29.02,60.54)
  BOTTOM w0.14: v1(29.02,60.54) 28.62,60.14 28.62,58.74 28.82,58.54 30.82,58.54 31.02,58.74 31.02,62.14 31.25,62.36 31.25,65.76 31.82,66.34 31.82,75.94 31.62,76.14 31.42,76.14 31.22,75.94 31.22,75.14 31.02,74.94 30.82,74.94 30.62,75.14 30.62,76.14 30.42,76.34 30.22,76.34 30.02,76.14 30.02,75.14 29.82,74.94 29.62,74.94 29.42,75.14 29.42,76.34 29.22,76.54 29.02,76.54 28.82,76.34 28.82,75.14 28.62,74.94 28.42,74.94 28.22,74.74 v1(28.22,74.34)
DMC0_DQ10: length 33.4
  TOP w0.14: U8.C8 v1(28.22,79.14)
  TOP w0.203: U1.B5 v1(28.22,60.54)
  BOTTOM w0.14: v1(28.22,60.54) 27.97,60.29 27.82,60.14 27.82,57.94 28.02,57.74 31.62,57.74 31.82,57.94 31.82,62.74 31.65,62.91 31.65,65.56 32.22,66.14 32.22,68.87 32.62,69.27 32.62,76.14 32.02,76.74 30.82,76.74 29.42,78.14 29.42,79.34 29.22,79.54 28.62,79.54 28.45,79.37 v1(28.22,79.14)
DMC0_DQ11: length 33.4
  TOP w0.14: U8.C2 v1(28.22,73.54)
  TOP w0.203: U1.A5 v1(28.22,61.34)
  BOTTOM w0.14: v1(28.22,61.34) 28.22,61.94 28.42,62.14 29.42,62.14 29.62,62.34 29.62,62.54 29.42,62.74 28.82,62.74 28.62,62.94 28.62,63.14 28.82,63.34 29.42,63.34 29.62,63.54 29.62,63.74 29.42,63.94 28.82,63.94 28.62,64.14 28.62,64.34 28.82,64.54 29.42,64.54 29.62,64.74 29.62,64.94 29.42,65.14 28.82,65.14 28.62,65.34 28.62,65.54 28.82,65.74 29.42,65.74 29.62,65.94 29.62,66.14 29.42,66.34 28.82,66.34 28.62,66.54 28.62,66.74 28.82,66.94 29.62,66.94 29.82,67.14 29.82,67.34 29.62,67.54 28.82,67.54 28.62,67.74 28.62,67.94 28.82,68.14 29.62,68.14 29.82,68.34 29.82,68.54 29.62,68.74 28.82,68.74 28.62,68.94 28.62,69.14 28.82,69.34 29.62,69.34 29.82,69.54 29.82,69.74 29.62,69.94 28.42,69.94 28.22,70.14 28.22,70.34 28.42,70.54 29.62,70.54 29.82,70.74 29.82,70.94 29.62,71.14 28.42,71.14 28.22,71.34 28.22,71.54 28.42,71.74 30.02,71.74 30.22,71.94 30.22,72.94 30.02,73.14 29.62,73.14 29.42,72.94 29.42,72.54 29.22,72.34 28.82,72.34 28.62,72.54 28.62,73.14 28.46,73.29 28.46,73.3 v1(28.22,73.54)
DMC0_DQ12: length 33.4
  TOP w0.14: U8.A7 v1(26.62,78.34)
  TOP w0.203: U1.A2 v1(25.82,61.34)
  BOTTOM w0.14: v1(25.82,61.34) 25.82,66.34 25.22,66.94 21.42,66.94 21.22,67.14 21.22,67.34 21.42,67.54 22.62,67.54 22.82,67.74 22.82,67.94 22.62,68.14 21.42,68.14 21.22,68.34 21.22,78.74 21.42,78.94 21.62,78.94 21.82,78.74 21.82,78.54 22.02,78.34 22.22,78.34 22.42,78.54 22.42,78.74 22.62,78.94 22.82,78.94 23.02,78.74 23.02,78.54 23.22,78.34 23.42,78.34 23.62,78.54 23.62,78.74 23.82,78.94 24.02,78.94 24.22,78.74 24.22,78.54 24.42,78.34 24.62,78.34 24.82,78.54 24.82,78.74 25.02,78.94 25.22,78.94 25.42,78.74 25.42,78.54 25.62,78.34 v1(26.62,78.34)
DMC0_DQ13: length 33.4
  TOP w0.14: U8.A2 v1(26.62,73.54)
  TOP w0.203: U1.B3 v1(26.62,60.54)
  BOTTOM w0.14: v1(26.62,73.54) 25.82,73.54 25.62,73.74 25.22,73.74 25.02,73.54 24.82,73.54 24.42,73.94 24.22,73.94 24.02,73.74 24.02,73.14 24.22,72.94 26.02,72.94 26.22,72.74 26.22,72.54 26.02,72.34 24.22,72.34 24.02,72.14 24.02,71.94 24.22,71.74 26.42,71.74 26.62,71.54 26.62,71.34 26.42,71.14 24.22,71.14 24.02,70.94 24.02,70.74 24.22,70.54 26.42,70.54 26.62,70.34 26.62,70.14 26.42,69.94 24.22,69.94 24.02,69.74 24.02,69.54 24.22,69.34 26.42,69.34 26.62,69.14 26.62,68.74 27.02,68.34 27.02,60.94 v1(26.62,60.54)
DMC0_DQ14: length 33.5
  TOP w0.14: U8.B8 v1(27.42,79.14)
  TOP w0.203: U1.D3 v1(26.62,58.94)
  BOTTOM w0.14: v1(26.62,58.94) 26.22,59.34 25.62,59.34 25.42,59.54 25.42,66.14 25.02,66.54 21.02,66.54 20.82,66.74 20.82,79.34 21.02,79.54 27.02,79.54 v1(27.42,79.14)
DMC0_DQ15: length 33.4
  TOP w0.14: U8.A3 v1(26.62,74.34)
  TOP w0.203: U1.A3 v1(26.62,61.34)
  BOTTOM w0.14: v1(26.62,61.34) 26.62,62.48 26.62,67.34 26.22,67.74 23.82,67.74 23.62,67.94 23.62,68.14 23.82,68.34 26.02,68.34 26.22,68.54 26.22,68.74 26.02,68.94 23.82,68.94 23.62,69.14 23.62,69.94 23.42,70.14 22.22,70.14 22.02,70.34 22.02,70.54 22.22,70.74 23.42,70.74 23.62,70.94 23.62,71.14 23.42,71.34 22.22,71.34 22.02,71.54 22.02,71.74 22.22,71.94 23.42,71.94 23.62,72.14 23.62,72.54 23.42,72.74 22.82,72.74 22.62,72.54 22.22,72.54 22.02,72.74 22.02,72.94 22.42,73.34 22.42,73.54 22.02,73.94 22.02,74.14 22.22,74.34 v1(26.62,74.34)
DMC0_LDM: length 33.4
  TOP w0.14: U8.E7 v1(29.82,78.34)
  TOP w0.203: U1.C1 v1(25.02,59.74)
  L4_SIG w0.127: v1(29.82,78.34) 29.82,77.74 30.02,77.54 30.22,77.54 30.42,77.74 30.62,77.74 30.82,77.54 32.02,77.54 32.22,77.34 32.22,77.14 32.02,76.94 29.42,76.94 29.22,77.14 29.22,77.34 29.02,77.54 28.82,77.54 28.62,77.34 28.62,77.14 28.42,76.94 28.22,76.94 28.02,77.14 28.02,77.34 27.82,77.54 27.62,77.54 27.42,77.34 27.42,77.14 27.22,76.94 27.02,76.94 26.82,77.14 26.82,77.74 26.62,77.94 26.42,77.94 26.22,77.74 26.22,77.14 26.02,76.94 24.62,76.94 24.42,76.74 24.42,66.34 25.02,65.74 25.02,62.14 24.42,61.54 24.42,60.34 v1(25.02,59.74)
DMC0_LDQS: length 33.2
  TOP w0.14: U8.F3 v1(30.62,74.34)
  TOP w0.203: U1.F2 v1(25.82,57.34)
  L4_SIG w0.076: v1(25.82,57.34) 26.14,57.02 U1.F2 27.62,56.94 27.82,57.14 27.82,61.72 27.56,61.98 27.56,66.42 26.16,67.82 26.16,69.6 26.29,69.72 27.3,69.72 27.56,69.98 27.56,70.48 27.3,70.74 26.29,70.74 26.16,70.87 26.16,71.12 26.29,71.25 27.56,71.25 27.81,71.5 27.81,72.01 27.56,72.26 26.29,72.26 26.16,72.39 26.16,75.18 26.29,75.31 27.05,75.31 27.18,75.18 28.07,75.18 28.19,75.31 30.73,75.31 30.86,75.18 30.86,74.55 v1(30.62,74.34)
DMC0_LDQS*: length 33.2
  TOP w0.14: U8.G3 v1(31.42,74.34)
  TOP w0.203: U1.F1 v1(25.02,57.34)
  L4_SIG w0.076: v1(25.02,57.34) 25.42,57.74 26.82,57.74 27.02,57.94 27.02,61.74 27.3,62.02 27.3,66.29 25.91,67.69 25.91,69.72 26.16,69.98 27.18,69.98 27.3,70.1 27.3,70.36 27.18,70.48 26.16,70.48 25.91,70.74 25.91,71.25 26.16,71.5 27.43,71.5 27.56,71.63 27.56,71.88 27.43,72.01 26.16,72.01 25.91,72.26 25.91,75.31 26.16,75.56 27.18,75.56 27.3,75.44 27.94,75.44 28.07,75.56 30.86,75.56 31.11,75.31 31.11,75.06 31.37,74.42 v1(31.42,74.34)
DMC0_ODT: length 41.4
  TOP w0.14: U8.K1 v1(33.82,72.74)
  TOP w0.203: U1.H19 v1(40.22,55.74)
  L4_SIG w0.127: v1(40.22,55.74) 40.5,56.02 40.62,56.14 41.42,56.14 41.62,55.94 41.62,55.54 41.42,55.34 40.02,55.34 39.82,55.54 39.82,56.74 40.02,56.94 40.42,56.94 40.62,57.14 40.62,57.54 39.62,58.54 37.62,58.54 37.42,58.34 37.42,57.94 37.22,57.74 36.82,57.74 36.62,57.94 36.62,58.34 36.42,58.54 36.02,58.54 35.82,58.34 35.82,57.94 35.62,57.74 35.22,57.74 35.02,57.94 35.02,58.34 34.82,58.54 33.62,58.54 33.42,58.34 33.22,58.34 33.02,58.54 33.02,66.34 33.42,66.74 33.42,72.34 v1(33.82,72.74)
  BOTTOM w0.14: v1(33.82,72.74) 33.42,72.34 33.42,71.94 33.82,71.54 34.42,71.54 34.62,71.34 34.62,71.14 34.42,70.94 34.02,70.94 33.82,71.14 33.62,71.14 33.42,70.94 33.42,70.74 33.62,70.54 34.42,70.54 34.62,70.34 34.62,70.14 34.42,69.94 34.02,69.94 33.82,70.14 33.62,70.14 33.42,69.94 33.42,69.59 33.7,69.31 RN6.2
DMC0_RAS*: length 41.4
  TOP w0.14: U8.J3 v1(33.02,74.34)
  TOP w0.203: U1.F19 v1(39.42,57.34)
  L4_SIG w0.127: v1(33.02,74.34) 32.62,73.94 32.62,67.54 31.82,66.74 31.82,56.34 32.02,56.14 32.42,56.14 32.62,56.34 32.62,56.54 32.72,56.64 33.22,56.64 33.42,56.44 33.42,55.54 33.62,55.34 35.52,55.34 35.72,55.54 35.72,55.94 35.92,56.14 36.42,56.14 36.62,55.94 36.62,55.54 36.82,55.34 37.22,55.34 37.42,55.54 37.42,55.94 37.62,56.14 38.02,56.14 38.22,55.94 38.22,55.54 38.42,55.34 38.82,55.34 39.02,55.54 39.02,56.94 v1(39.42,57.34)
  BOTTOM w0.14: v1(33.02,74.34) 33.02,75.34 33.22,75.54 33.42,75.54 33.62,75.34 33.62,74.94 U8.J3 33.42,73.34 33.02,72.94 33.02,68.66 RN6.1
DMC0_RESET*: length 31.9
  TOP w0.14: R8.2 39.22,71.94 39.52,72.24 39.52,73.44 U8.T2 v1(38.62,73.54) ; U1.B12 33.82,60.54 33.82,61.54 34.42,62.14 34.42,66.17 34.93,66.67 42.36,66.67 43.22,67.53 v1(43.22,71.37)
  BOTTOM w0.14: 42.56,71.63 42.81,71.37 v1(43.22,71.37) ; 42.56,71.63 42.27,71.34 39.22,71.34 39.02,71.54 39.02,73.14 38.87,73.29 v1(38.62,73.54) ; 42.56,71.63 42.56,72.44 42.15,72.85 RN2.1
DMC0_RZQ: length 4.7
  TOP w0.203: U1.G19 v1(40.22,56.54)
  BOTTOM w0.14: v1(40.22,56.54) 41.5,56.54 43.1,54.94 R1.1
DMC0_UDM: length 33.4
  TOP w0.14: U8.D3 v1(29.02,74.34)
  TOP w0.203: U1.A6 v1(29.02,61.34)
  BOTTOM w0.14: v1(29.02,74.34) 29.26,74.1 29.26,74.09 29.42,73.94 30.82,73.94 31.02,73.74 31.02,72.54 30.62,72.14 30.62,71.94 30.82,71.74 30.92,71.74 31.12,71.94 31.22,71.94 31.42,71.74 31.42,71.14 31.22,70.94 30.82,70.94 30.62,71.14 30.42,71.14 30.22,70.94 30.22,70.74 30.42,70.54 31.22,70.54 31.42,70.34 31.42,70.14 31.22,69.94 30.42,69.94 30.22,69.74 30.22,69.19 30.45,68.96 31.25,68.96 31.45,68.76 31.45,68.56 31.25,68.36 30.45,68.36 30.25,68.16 30.25,67.96 30.45,67.76 31.25,67.76 31.45,67.56 31.45,67.36 31.25,67.16 30.45,67.16 30.25,66.96 30.25,66.76 30.45,66.56 30.85,66.56 31.05,66.36 31.05,66.16 30.85,65.96 30.25,65.96 30.05,65.76 30.05,65.56 30.25,65.36 30.65,65.36 30.85,65.16 30.85,64.96 30.65,64.76 30.25,64.76 30.05,64.56 30.05,64.36 30.25,64.16 30.65,64.16 30.85,63.96 30.85,63.76 30.65,63.56 30.25,63.56 30.05,63.36 30.05,63.16 30.25,62.96 30.65,62.96 30.85,62.76 30.85,62.56 30.65,62.36 30.25,62.36 30.05,62.16 30.05,61.91 30.22,61.74 30.22,59.54 30.02,59.34 29.62,59.34 29.42,59.54 U1.A6 v1(29.02,61.34)
DMC0_UDQS: length 33.4
  TOP w0.14: U8.C7 v1(28.22,78.34)
  TOP w0.203: U1.B4 v1(27.42,60.54)
  BOTTOM w0.089: v1(28.22,78.34) 28.55,77.93 28.55,77.37 27.57,76.39 25.34,76.39 24.64,77.09 22.54,77.09 22.4,76.95 22.4,75.55 22.54,75.41 22.96,75.41 23.1,75.55 23.1,76.25 23.38,76.53 23.94,76.53 24.22,76.25 24.22,75.55 24.36,75.41 25.9,75.41 26.31,75.83 27.29,75.83 27.57,75.55 27.57,75.1 27.82,74.85 27.82,72.34 27.57,72.09 27.57,69.27 27.99,68.85 27.99,62.42 27.82,62.25 27.82,60.94 27.7,60.82 v1(27.42,60.54)
DMC0_UDQS*: length 33.4
  TOP w0.14: U8.B7 v1(27.42,78.34)
  TOP w0.203: U1.A4 v1(27.42,61.34)
  BOTTOM w0.089: v1(27.42,78.34) 27.42,77.98 27.42,77.8 27.57,77.65 27.76,77.65 27.99,77.88 28.13,77.88 28.27,77.74 28.27,77.51 27.43,76.67 25.48,76.67 24.78,77.37 22.4,77.37 22.12,77.09 22.12,75.41 22.4,75.13 23.1,75.13 23.38,75.41 23.38,76.11 23.52,76.25 23.8,76.25 23.94,76.11 23.94,75.41 24.22,75.13 26.04,75.13 26.45,75.55 27.15,75.55 27.29,75.41 27.29,75.13 27.02,74.85 27.02,72.34 27.29,72.07 27.29,69.13 27.71,68.71 27.71,62.57 27.42,62.28 v1(27.42,61.34)
DMC0_VREF: length 2.3
  BOTTOM w0.406: 44.7,56.54 v1(45.42,56.54) 47.02,56.54
  vias: v2(44.83,65.53)
DMC0_WE*: length 41.3
  TOP w0.14: U8.L3 v1(34.62,74.34)
  TOP w0.203: U1.A12 v1(34.62,61.34)
  L4_SIG w0.127: v1(34.62,74.34) 34.62,74.94 34.82,75.14 35.22,75.14 35.42,74.94 36.02,74.94 36.22,75.14 36.22,75.34 36.02,75.54 34.42,75.54 34.22,75.34 34.22,72.54 33.82,72.14 33.82,70.94 34.02,70.74 35.62,70.74 35.82,70.54 35.82,70.34 35.62,70.14 35.02,70.14 34.82,70.34 34.02,70.34 33.82,70.14 33.82,69.94 34.02,69.74 35.62,69.74 35.82,69.54 35.82,69.34 35.62,69.14 35.22,69.14 35.02,69.34 34.02,69.34 33.82,69.14 33.82,66.34 33.42,65.94 33.42,59.54 33.62,59.34 34.02,59.34 34.22,59.54 U1.A12 34.62,61.34 v1(34.62,61.34)
  BOTTOM w0.14: RN1.3 42.07,77.19 42.01,77.19 37.47,77.19 v1(34.62,74.34)
FPLL_VDDHV: length 39.7
  TOP w0.203: U1.N5 v1(28.22,50.94)
  TOP w0.508: v1(49.66,46.86) C240.1 49.7,46.01 C239.1 50.88,46.06 FL3.3
  L8_SIG w0.127: 28.61,50.55 v1(28.22,50.94) 28.61,51.33 30.59,51.33 30.99,50.93 30.61,50.55 28.61,50.55
  L8_SIG w0.14: 36.7,50.55 41.53,50.55 41.91,50.93 41.5,51.33 36.73,51.33 36.32,50.93 36.7,50.55
  L8_SIG w0.508: 36.32,50.93 30.99,50.93 ; 41.91,50.93 49.15,50.93 49.66,50.42 v1(49.66,46.86)
HADC0_VIN0: length 41.4
  TOP w0.203: U1.N19 v1(40.22,50.94)
  L4_SIG w0.127: v1(40.22,50.94) 40.61,50.55 48.42,50.55 48.44,50.57 52.42,50.57 55.4,47.6 55.4,39.09 60.3,34.18 60.3,28.85 v1(61.72,27.43)
  BOTTOM w0.14: v1(61.72,27.43) J1.47
HADC0_VIN1: length 40.2
  TOP w0.203: U1.N20 v1(41.02,50.94)
  L4_SIG w0.127: v1(61.72,28.07) 60.63,29.16 60.63,34.32 55.73,39.22 55.73,47.73 52.52,50.94 v1(41.02,50.94)
  BOTTOM w0.14: v1(61.72,28.07) J1.49
HADC0_VIN2: length 41
  TOP w0.203: U1.M19 v1(40.22,51.74)
  L4_SIG w0.127: v1(61.72,28.7) 60.96,29.46 60.96,34.46 56.06,39.36 56.06,47.87 52.62,51.31 48.44,51.31 48.42,51.33 40.63,51.33 v1(40.22,51.74)
  BOTTOM w0.14: J1.51 v1(61.72,28.7)
HADC0_VIN3: length 40.2
  TOP w0.203: U1.M20 v1(41.02,51.74)
  L4_SIG w0.127: v1(61.72,29.34) 61.29,29.77 61.29,34.59 56.39,39.5 56.39,48.01 52.71,51.69 49.53,51.69 49.02,52.2 41.48,52.2 v1(41.02,51.74)
  BOTTOM w0.14: v1(61.72,29.34) J1.53
